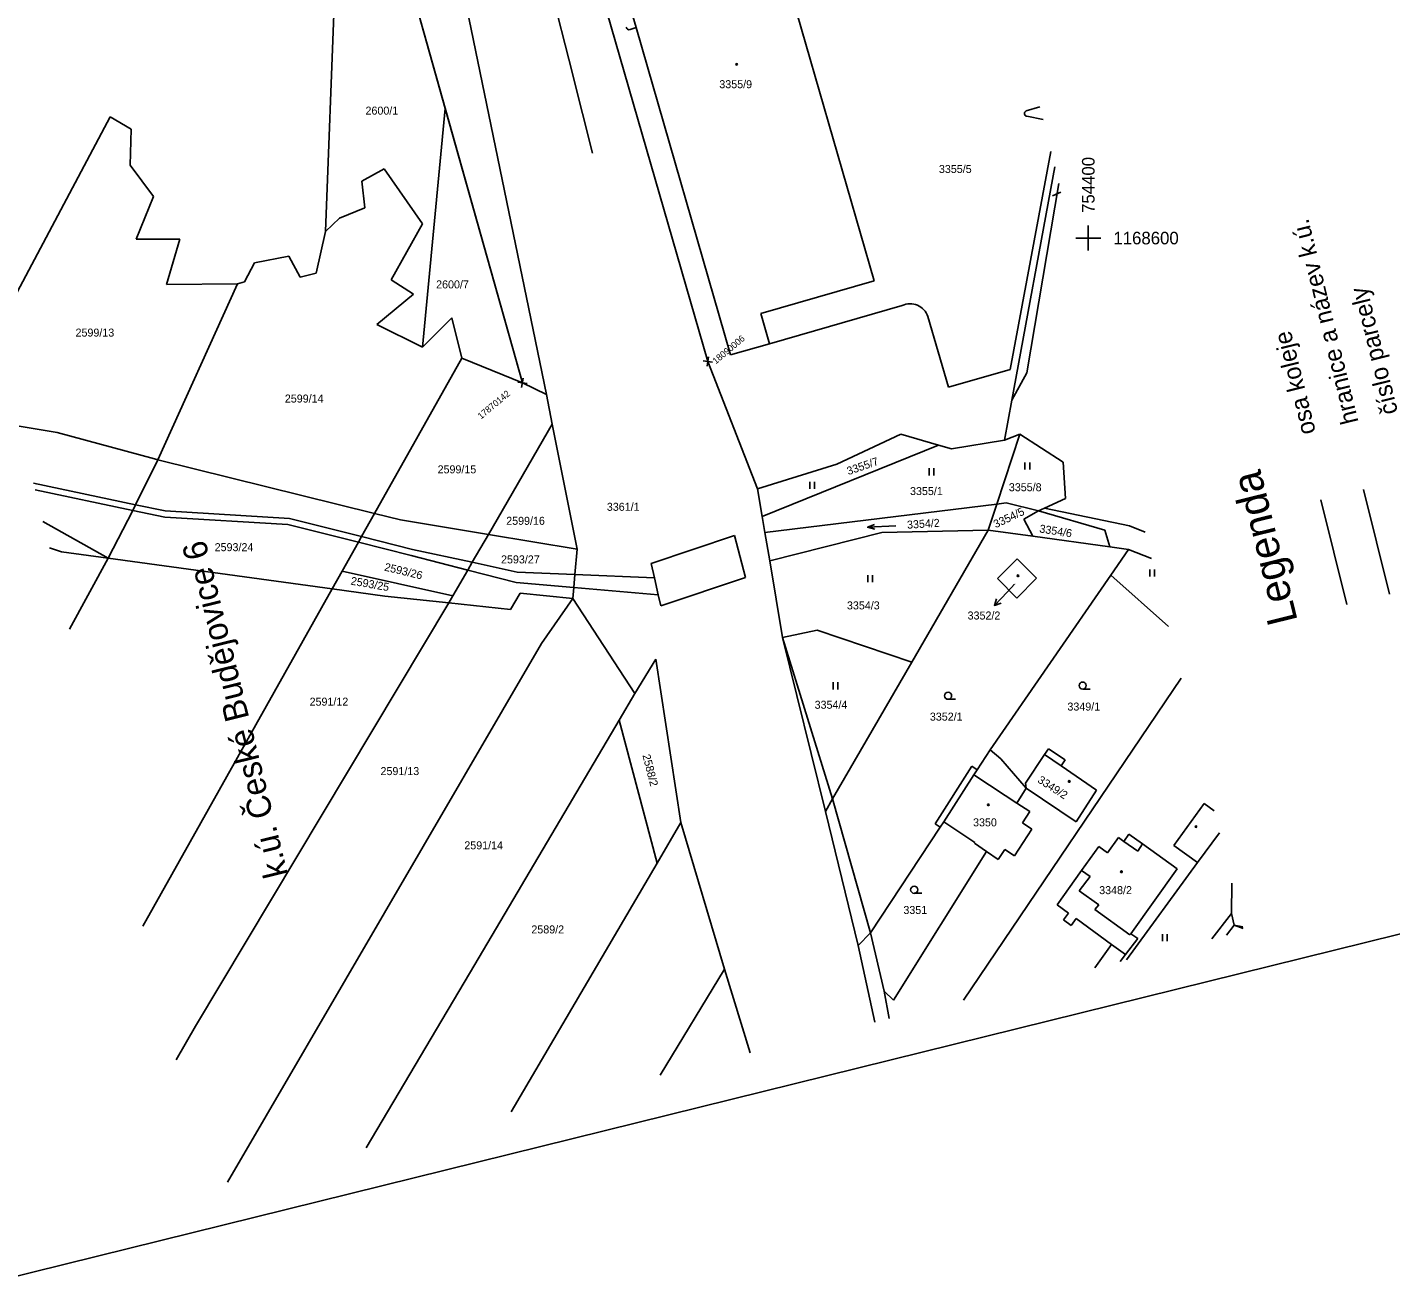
# Model space of a CAD drawing. Extents: x -754679 to -754173, y -1169241 to -1168288.
# Drawn here: x -754569 to -754351.8, y -1168767.3 to -1168566.4 of the extents above; entities that cross this region are included whole.
import ezdxf

# ---------------------------------------------------------------- set-up
doc = ezdxf.new("R2010")
doc.units = 0
for name, color, linetype in [('Default', 7, 'Continuous'), ('Vrstva 1', 7, 'Continuous'), ('Vrstva 16', 7, 'Continuous'), ('Vrstva 18', 7, 'Continuous'), ('Vrstva 19', 7, 'Continuous'), ('Vrstva 24', 7, 'Continuous'), ('Vrstva 25', 7, 'Continuous'), ('Vrstva 27', 7, 'Continuous'), ('Vrstva 4', 7, 'Continuous'), ('Vrstva 52', 7, 'Continuous'), ('Vrstva 53', 7, 'Continuous'), ('Vrstva 6', 7, 'Continuous'), ('Vrstva 60', 7, 'Continuous'), ('Vrstva 61', 7, 'Continuous')]:
    doc.layers.add(name, color=color, linetype=linetype)

msp = doc.modelspace()

# ---------------------------------------------------------------- linework, layer by layer
at = {"layer": 'Default'}
for points in [[(-754400, -1168602), (-754400, -1168600), (-754400, -1168598)], [(-754402, -1168600), (-754400, -1168600), (-754398, -1168600)]]:
    msp.add_lwpolyline(points, dxfattribs=at)
at = {"layer": 'Vrstva 1'}
for p, q in [((-754519.8, -1168462.41), (-754486.32, -1168624.94)), ((-754502.42, -1168579.34), (-754515.13, -1168534.05)), ((-754483.21, -1168541.23), (-754460.6, -1168619.67)), ((-754472.02, -1168566.47), (-754478.33, -1168544.59)), ((-754447.41, -1168560.64), (-754434.1, -1168606.84)), ((-754472.98, -1168566.77), (-754472.02, -1168566.47)), ((-754456.98, -1168618.63), (-754472.02, -1168566.47)), ((-754490.14, -1168623.07), (-754502.42, -1168579.34)), ((-754409.87, -1168579.74), (-754407.71, -1168579.09)), ((-754407.21, -1168581.12), (-754409.78, -1168580.6)), ((-754412.42, -1168620.92), (-754405.96, -1168586.18)), ((-754405.35, -1168588.64), (-754412.19, -1168625.83)), ((-754404.69, -1168591.31), (-754409.8, -1168621.48)), ((-754434.1, -1168606.84), (-754452.14, -1168612.04)), ((-754452.14, -1168612.04), (-754450.76, -1168616.84)), ((-754450.76, -1168616.84), (-754429.64, -1168610.75)), ((-754425.55, -1168612.51), (-754422.27, -1168623.78)), ((-754450.76, -1168616.84), (-754456.98, -1168618.63)), ((-754460.6, -1168619.67), (-754452.67, -1168639.96)), ((-754422.27, -1168623.78), (-754412.42, -1168620.92)), ((-754409.8, -1168621.48), (-754412.19, -1168625.83)), ((-754490.14, -1168623.07), (-754486.32, -1168624.94)), ((-754486.32, -1168624.94), (-754485.38, -1168629.68)), ((-754412.19, -1168625.83), (-754413.36, -1168632.2)), ((-754570.29, -1168629.95), (-754564.24, -1168630.96)), ((-754564.24, -1168630.96), (-754548.76, -1168635.2)), ((-754485.38, -1168629.68), (-754481.43, -1168649.55)), ((-754440.06, -1168636.05), (-754429.88, -1168631.27)), ((-754429.88, -1168631.27), (-754423.86, -1168633.01)), ((-754413.36, -1168632.2), (-754410.89, -1168631.27)), ((-754410.89, -1168631.27), (-754404, -1168635.7)), ((-754423.86, -1168633.01), (-754421.81, -1168633.6)), ((-754421.81, -1168633.6), (-754413.36, -1168632.2)), ((-754548.23, -1168635.33), (-754548.76, -1168635.2)), ((-754513.7, -1168643.9), (-754548.23, -1168635.33)), ((-754404, -1168635.7), (-754403.6, -1168641.5)), ((-754452.67, -1168639.96), (-754440.06, -1168636.05)), ((-754452.67, -1168639.96), (-754451.93, -1168644.34)), ((-754414.55, -1168642.38), (-754451.5, -1168646.92)), ((-754413.07, -1168642.2), (-754414.55, -1168642.38)), ((-754407.94, -1168643.48), (-754413.07, -1168642.2)), ((-754403.6, -1168641.5), (-754406.98, -1168643.04)), ((-754509.58, -1168644.92), (-754513.7, -1168643.9)), ((-754451.93, -1168644.34), (-754451.5, -1168646.92)), ((-754406.98, -1168643.04), (-754407.94, -1168643.48)), ((-754406.98, -1168643.04), (-754393.41, -1168645.86)), ((-754495.56, -1168647.23), (-754509.58, -1168644.92)), ((-754432.9, -1168646.9), (-754415.92, -1168646.53)), ((-754415.92, -1168646.53), (-754428.1, -1168667.57)), ((-754408.83, -1168647.52), (-754415.92, -1168646.53)), ((-754393.41, -1168645.86), (-754390.96, -1168646.85)), ((-754481.43, -1168649.55), (-754495.56, -1168647.23)), ((-754451.5, -1168646.92), (-754450.74, -1168651.41)), ((-754432.9, -1168646.9), (-754450.74, -1168651.41)), ((-754396.58, -1168649.22), (-754408.83, -1168647.52)), ((-754563.56, -1168649.98), (-754565.48, -1168649.38)), ((-754563.56, -1168649.98), (-754556.15, -1168651.01)), ((-754556.15, -1168651.01), (-754520.42, -1168655.89)), ((-754481.43, -1168649.55), (-754481.76, -1168653.61)), ((-754411.33, -1168651.11), (-754414.47, -1168654.27)), ((-754408.23, -1168654.21), (-754411.33, -1168651.11)), ((-754393.6, -1168649.63), (-754396.58, -1168649.22)), ((-754393.6, -1168649.63), (-754396.4, -1168653.69)), ((-754393.6, -1168649.63), (-754389.92, -1168651.06)), ((-754448.68, -1168663.63), (-754450.74, -1168651.41)), ((-754481.76, -1168653.61), (-754481.94, -1168655.69)), ((-754396.4, -1168653.69), (-754415.64, -1168681.53)), ((-754414.47, -1168654.27), (-754411.38, -1168657.36)), ((-754411.38, -1168657.36), (-754408.23, -1168654.21)), ((-754396.4, -1168653.69), (-754387.23, -1168661.91)), ((-754520.42, -1168655.89), (-754512.05, -1168657.04)), ((-754512.05, -1168657.04), (-754501.88, -1168658.12)), ((-754492.02, -1168659.16), (-754490.52, -1168656.57)), ((-754490.52, -1168656.57), (-754482.08, -1168657.45)), ((-754481.94, -1168655.69), (-754482.08, -1168657.45)), ((-754472.22, -1168672.58), (-754482.08, -1168657.45)), ((-754501.88, -1168658.12), (-754492.02, -1168659.16)), ((-754448.68, -1168663.63), (-754441.87, -1168691.36)), ((-754468.86, -1168667.12), (-754472.22, -1168672.58)), ((-754464.89, -1168693.12), (-754468.86, -1168667.12)), ((-754428.1, -1168667.57), (-754440.72, -1168689.36)), ((-754385.2, -1168670.12), (-754419.89, -1168721.45)), ((-754472.22, -1168672.58), (-754474.73, -1168676.83)), ((-754497.71, -1168715.77), (-754474.73, -1168676.83)), ((-754474.73, -1168676.83), (-754468.68, -1168699.59)), ((-754415.64, -1168681.53), (-754417.68, -1168684.71)), ((-754415.64, -1168681.53), (-754413.94, -1168682.99)), ((-754406.97, -1168682.3), (-754406.35, -1168681.37)), ((-754406.35, -1168681.37), (-754403.66, -1168683.16)), ((-754413.94, -1168682.99), (-754409.88, -1168687.67)), ((-754410.01, -1168686.86), (-754406.97, -1168682.3)), ((-754403.66, -1168683.16), (-754404.29, -1168684.1)), ((-754418.53, -1168684.17), (-754424.41, -1168693.34)), ((-754417.68, -1168684.71), (-754418.53, -1168684.17)), ((-754404.29, -1168684.1), (-754398.67, -1168687.96)), ((-754409.88, -1168687.67), (-754411.36, -1168690.04)), ((-754409.88, -1168687.67), (-754410.01, -1168686.86)), ((-754401.94, -1168693.01), (-754409.88, -1168687.67)), ((-754398.67, -1168687.96), (-754401.94, -1168693.01)), ((-754440.72, -1168689.36), (-754441.87, -1168691.36)), ((-754411.36, -1168690.04), (-754409.3, -1168691.38)), ((-754381.55, -1168690.12), (-754386.35, -1168696.77)), ((-754379.97, -1168691.28), (-754381.55, -1168690.12)), ((-754436.63, -1168712.73), (-754441.87, -1168691.36)), ((-754409.3, -1168691.38), (-754410.48, -1168693.2)), ((-754468.68, -1168699.59), (-754464.89, -1168693.12)), ((-754464.89, -1168693.12), (-754457.95, -1168716.5)), ((-754423.57, -1168693.88), (-754434.7, -1168710.71)), ((-754424.41, -1168693.34), (-754423.57, -1168693.88)), ((-754423.03, -1168693.04), (-754423.57, -1168693.88)), ((-754418.08, -1168696.32), (-754423.03, -1168693.04)), ((-754408.98, -1168694.18), (-754411.76, -1168698.45)), ((-754410.48, -1168693.2), (-754408.98, -1168694.18)), ((-754418.1, -1168696.41), (-754418.08, -1168696.32)), ((-754416.19, -1168697.75), (-754418.1, -1168696.41)), ((-754395.18, -1168695.53), (-754396.93, -1168697.95)), ((-754394.33, -1168696.13), (-754395.18, -1168695.53)), ((-754393.52, -1168694.99), (-754394.33, -1168696.13)), ((-754391.34, -1168696.54), (-754393.52, -1168694.99)), ((-754385.86, -1168700.53), (-754391.34, -1168696.54)), ((-754386.35, -1168696.77), (-754382.58, -1168699.52)), ((-754382.58, -1168699.52), (-754379.11, -1168694.75)), ((-754416.19, -1168697.75), (-754431.01, -1168721.45)), ((-754414.34, -1168699.04), (-754416.19, -1168697.75)), ((-754413.3, -1168697.45), (-754414.34, -1168699.04)), ((-754411.76, -1168698.45), (-754413.3, -1168697.45)), ((-754398.33, -1168696.96), (-754401.06, -1168700.75)), ((-754396.93, -1168697.95), (-754398.33, -1168696.96)), ((-754491.91, -1168739.25), (-754468.68, -1168699.59)), ((-754401.06, -1168700.75), (-754404.95, -1168706.25)), ((-754393.89, -1168715.02), (-754382.58, -1168699.52)), ((-754393.21, -1168710.84), (-754385.86, -1168700.53)), ((-754377.12, -1168702.79), (-754377.2, -1168707.6)), ((-754404.95, -1168706.25), (-754403.16, -1168707.56)), ((-754403.16, -1168707.56), (-754403.96, -1168708.65)), ((-754377.2, -1168707.6), (-754380.33, -1168711.66)), ((-754376.74, -1168709.5), (-754377.2, -1168707.6)), ((-754403.96, -1168708.65), (-754402.75, -1168709.54)), ((-754402.75, -1168709.54), (-754401.95, -1168708.44)), ((-754401.95, -1168708.44), (-754396.29, -1168712.57)), ((-754376.74, -1168709.5), (-754375.34, -1168710.03)), ((-754434.7, -1168710.71), (-754436.63, -1168712.73)), ((-754434.7, -1168710.71), (-754432.51, -1168719.99)), ((-754394.09, -1168714.17), (-754392.08, -1168711.61)), ((-754392.08, -1168711.61), (-754393.21, -1168710.84)), ((-754436.63, -1168712.73), (-754433.99, -1168724.93)), ((-754398.96, -1168716.27), (-754396.29, -1168712.57)), ((-754396.29, -1168712.57), (-754394.09, -1168714.17)), ((-754394.09, -1168714.17), (-754394.9, -1168715.27)), ((-754515.02, -1168744.97), (-754497.71, -1168715.77)), ((-754457.95, -1168716.5), (-754468.2, -1168733.39)), ((-754457.95, -1168716.5), (-754453.86, -1168729.85)), ((-754431.01, -1168721.45), (-754432.51, -1168719.99)), ((-754545.31, -1168730.96), (-754542.2, -1168725.58))]:
    msp.add_line(p, q, dxfattribs=at)
msp.add_lwpolyline([(-754478.97, -1168586.46), (-754480.56, -1168580.17), (-754482.76, -1168571.47), (-754485.13, -1168562.12), (-754486.61, -1168556.26), (-754487.79, -1168551.61), (-754490, -1168542.89), (-754492.27, -1168533.93), (-754493.96, -1168527.25), (-754496.18, -1168518.51), (-754498.39, -1168509.75)], dxfattribs=at)
for centre, radius, start, end in [((-754473.14, -1168566.34), 0.458, 188.7847, 290.1201), ((-754409.71, -1168580.16), 0.449, 111.4818, 260.4669), ((-754428.36, -1168613.4), 2.94, 17.5572, 115.8766)]:
    msp.add_arc(centre, radius, start, end, dxfattribs=at)
at = {"layer": 'Vrstva 16'}
for p, q in [((-754405.69, -1168593.28), (-754404.35, -1168592.69)), ((-754411.74, -1168655.16), (-754412.88, -1168656.36)), ((-754414.94, -1168658.54), (-754412.88, -1168656.36))]:
    msp.add_line(p, q, dxfattribs=at)
msp.add_lwpolyline([(-754413.89, -1168658.16), (-754414.94, -1168658.54), (-754414.62, -1168657.47)], dxfattribs=at)
at = {"layer": 'Vrstva 24'}
msp.add_line((-754352.02, -1168656.73), (-754356.14, -1168640.06), dxfattribs=at)
at = {"layer": 'Vrstva 25'}
for p, q in [((-754410.08, -1168636.9), (-754410.08, -1168635.78)), ((-754409.33, -1168636.9), (-754409.33, -1168635.78)), ((-754425.35, -1168637.81), (-754425.35, -1168636.69)), ((-754424.6, -1168637.81), (-754424.6, -1168636.69)), ((-754444.36, -1168639.95), (-754444.36, -1168638.82)), ((-754443.61, -1168639.95), (-754443.61, -1168638.82)), ((-754390.18, -1168653.94), (-754390.18, -1168652.81)), ((-754389.43, -1168653.94), (-754389.43, -1168652.81)), ((-754435.1, -1168654.85), (-754435.1, -1168653.73)), ((-754434.35, -1168654.85), (-754434.35, -1168653.73)), ((-754440.64, -1168671.92), (-754440.64, -1168670.79)), ((-754439.89, -1168671.92), (-754439.89, -1168670.79)), ((-754400.89, -1168671.86), (-754399.69, -1168671.86)), ((-754422.33, -1168673.49), (-754421.13, -1168673.49)), ((-754427.73, -1168704.41), (-754426.53, -1168704.41)), ((-754388.2, -1168712.05), (-754388.2, -1168710.93)), ((-754387.45, -1168712.05), (-754387.45, -1168710.93))]:
    msp.add_line(p, q, dxfattribs=at)
for points in [[(-754435.14, -1168646.09), (-754434.03, -1168645.66)], [(-754430.64, -1168645.85), (-754435.14, -1168646.09), (-754433.99, -1168646.41)]]:
    msp.add_lwpolyline(points, dxfattribs=at)
for centre, radius in [((-754456.02, -1168572.33), 0.131), ((-754411.19, -1168653.81), 0.131), ((-754400.89, -1168671.3), 0.562), ((-754422.33, -1168672.93), 0.562), ((-754403.03, -1168686.58), 0.131), ((-754415.93, -1168690.31), 0.131), ((-754382.84, -1168693.79), 0.131), ((-754394.71, -1168700.98), 0.131), ((-754427.73, -1168703.85), 0.562)]:
    msp.add_circle(centre, radius, dxfattribs=at)
at = {"layer": 'Vrstva 27'}
msp.add_line((-754358.81, -1168658.41), (-754362.94, -1168641.73), dxfattribs=at)
at = {"layer": 'Vrstva 4'}
for p, q in [((-754568.04, -1168639.05), (-754551.77, -1168642.49)), ((-754567.77, -1168640.13), (-754552.22, -1168643.4)), ((-754551.77, -1168642.49), (-754547.06, -1168643.48)), ((-754552.22, -1168643.4), (-754547.12, -1168644.47)), ((-754547.12, -1168644.47), (-754527.5, -1168645.65)), ((-754547.06, -1168643.48), (-754527.26, -1168644.67)), ((-754527.26, -1168644.67), (-754515.75, -1168647.56)), ((-754527.5, -1168645.65), (-754516.26, -1168648.47)), ((-754516.26, -1168648.47), (-754507.88, -1168650.57)), ((-754515.75, -1168647.56), (-754507.64, -1168649.6)), ((-754469.63, -1168651.87), (-754456.36, -1168647.37)), ((-754456.36, -1168647.37), (-754454.61, -1168654.08)), ((-754507.88, -1168650.57), (-754498.85, -1168652.9)), ((-754507.64, -1168649.6), (-754498.13, -1168651.66)), ((-754498.85, -1168652.9), (-754491.11, -1168654.89)), ((-754498.13, -1168651.66), (-754490.96, -1168653.21)), ((-754490.96, -1168653.21), (-754481.76, -1168653.61)), ((-754469.63, -1168651.87), (-754469.11, -1168654.15)), ((-754491.11, -1168654.89), (-754481.94, -1168655.69)), ((-754481.76, -1168653.61), (-754469.11, -1168654.15)), ((-754469.11, -1168654.15), (-754468.49, -1168656.87)), ((-754468.1, -1168658.6), (-754454.61, -1168654.08)), ((-754481.94, -1168655.69), (-754468.49, -1168656.87)), ((-754468.1, -1168658.6), (-754468.49, -1168656.87)), ((-754440.72, -1168689.36), (-754448.68, -1168663.63)), ((-754406.97, -1168682.3), (-754404.29, -1168684.1)), ((-754418.22, -1168685.55), (-754423.03, -1168693.04)), ((-754417.68, -1168684.71), (-754418.22, -1168685.55)), ((-754418.22, -1168685.55), (-754413.25, -1168688.81)), ((-754440.72, -1168689.36), (-754434.7, -1168710.71)), ((-754413.25, -1168688.81), (-754411.36, -1168690.04)), ((-754392.13, -1168697.71), (-754394.33, -1168696.13)), ((-754391.34, -1168696.54), (-754392.13, -1168697.71)), ((-754401.06, -1168700.75), (-754399.72, -1168701.74)), ((-754399.72, -1168701.74), (-754401.46, -1168704.02)), ((-754401.46, -1168704.02), (-754398.34, -1168706.25)), ((-754398.34, -1168706.25), (-754398.97, -1168706.99)), ((-754398.97, -1168706.99), (-754393.36, -1168711.05)), ((-754377.98, -1168711.08), (-754376.74, -1168709.5)), ((-754393.36, -1168711.05), (-754393.21, -1168710.84)), ((-754431.69, -1168724.36), (-754432.51, -1168719.99))]:
    msp.add_line(p, q, dxfattribs=at)
at = {"layer": 'Vrstva 53'}
for p, q in [((-754490.14, -1168623.07), (-754523.85, -1168502.96)), ((-754483.21, -1168541.23), (-754460.6, -1168619.67))]:
    msp.add_line(p, q, dxfattribs=at)
at = {"layer": 'Vrstva 6'}
for p, q in [((-754521.52, -1168598.96), (-754519.11, -1168536.88)), ((-754506.06, -1168617.39), (-754502.42, -1168579.34)), ((-754574, -1168614.95), (-754555.83, -1168580.68)), ((-754555.83, -1168580.68), (-754552.45, -1168582.65)), ((-754552.45, -1168582.65), (-754552.61, -1168588.39)), ((-754552.61, -1168588.39), (-754548.9, -1168593.37)), ((-754515.73, -1168590.96), (-754512.18, -1168588.99)), ((-754512.18, -1168588.99), (-754506.06, -1168597.75)), ((-754515.24, -1168595.19), (-754515.73, -1168590.96)), ((-754548.9, -1168593.37), (-754551.64, -1168600.17)), ((-754521.52, -1168598.96), (-754519.27, -1168596.85)), ((-754519.27, -1168596.85), (-754515.24, -1168595.19)), ((-754522.97, -1168605.61), (-754521.52, -1168598.96)), ((-754506.06, -1168597.75), (-754511.06, -1168606.67)), ((-754551.64, -1168600.17), (-754544.72, -1168600.17)), ((-754544.72, -1168600.17), (-754546.81, -1168607.42)), ((-754532.8, -1168603.95), (-754527.32, -1168602.89)), ((-754527.32, -1168602.89), (-754525.55, -1168606.21)), ((-754534.41, -1168606.97), (-754532.8, -1168603.95)), ((-754548.23, -1168635.33), (-754535.54, -1168607.27)), ((-754546.81, -1168607.42), (-754535.54, -1168607.27)), ((-754535.54, -1168607.27), (-754534.41, -1168606.97)), ((-754525.55, -1168606.21), (-754522.97, -1168605.61)), ((-754511.06, -1168606.67), (-754507.51, -1168608.93)), ((-754507.51, -1168608.93), (-754513.31, -1168613.76)), ((-754513.31, -1168613.76), (-754506.06, -1168617.39)), ((-754506.06, -1168617.39), (-754501.39, -1168612.71)), ((-754501.39, -1168612.71), (-754499.81, -1168619.14)), ((-754499.81, -1168619.14), (-754513.7, -1168643.9)), ((-754499.81, -1168619.14), (-754490.14, -1168623.07)), ((-754485.38, -1168629.68), (-754495.56, -1168647.23)), ((-754410.89, -1168631.27), (-754414.55, -1168642.38)), ((-754451.93, -1168644.34), (-754423.86, -1168633.01)), ((-754551.77, -1168642.49), (-754548.23, -1168635.33)), ((-754552.22, -1168643.4), (-754551.77, -1168642.49)), ((-754414.55, -1168642.38), (-754415.92, -1168646.53)), ((-754552.22, -1168643.4), (-754556.15, -1168651.01)), ((-754513.7, -1168643.9), (-754515.75, -1168647.56)), ((-754407.94, -1168643.48), (-754410.28, -1168644.8)), ((-754397.37, -1168646.53), (-754407.94, -1168643.48)), ((-754566.53, -1168645.15), (-754556.15, -1168651.01)), ((-754410.28, -1168644.8), (-754408.83, -1168647.52)), ((-754396.58, -1168649.22), (-754397.37, -1168646.53)), ((-754516.26, -1168648.47), (-754518.85, -1168653.1)), ((-754515.75, -1168647.56), (-754516.26, -1168648.47)), ((-754495.56, -1168647.23), (-754498.13, -1168651.66)), ((-754562.29, -1168662.3), (-754556.15, -1168651.01)), ((-754518.85, -1168653.1), (-754520.42, -1168655.89)), ((-754518.85, -1168653.1), (-754501.23, -1168657.01)), ((-754498.85, -1168652.9), (-754501.23, -1168657.01)), ((-754498.13, -1168651.66), (-754498.85, -1168652.9)), ((-754520.42, -1168655.89), (-754550.58, -1168709.63)), ((-754501.23, -1168657.01), (-754501.88, -1168658.12)), ((-754482.08, -1168657.45), (-754487.11, -1168664.61)), ((-754542.2, -1168725.58), (-754501.88, -1168658.12)), ((-754448.68, -1168663.63), (-754443.21, -1168662.48)), ((-754443.21, -1168662.48), (-754428.1, -1168667.57)), ((-754487.11, -1168664.61), (-754537.11, -1168750.43)), ((-754375.4, -1168709.77), (-754376.74, -1168709.5))]:
    msp.add_line(p, q, dxfattribs=at)
at = {"layer": 'Vrstva 60'}
for p, q in [((-754461.34, -1168619.54), (-754459.86, -1168619.8)), ((-754460.47, -1168618.93), (-754460.73, -1168620.41)), ((-754490.88, -1168622.94), (-754489.4, -1168623.2)), ((-754490.01, -1168622.33), (-754490.27, -1168623.81))]:
    msp.add_line(p, q, dxfattribs=at)
at = {"layer": 'Vrstva 61'}
msp.add_lwpolyline([(-754578.24, -1168767.26), (-754289.93, -1168695.96), (-754390.75, -1168288.24), (-754679.07, -1168359.54)], dxfattribs=at)

# ---------------------------------------------------------------- texts
at = {"layer": 'Default'}
msp.add_text('754400', height=2, rotation=90, dxfattribs=at).set_placement((-754399, -1168596))
msp.add_text('1168600', height=2, dxfattribs=at).set_placement((-754396, -1168601))
at = {"layer": 'Vrstva 16'}
msp.add_text('3352/2', height=1.275, rotation=360, dxfattribs=at).set_placement((-754419.22, -1168660.78))
at = {"layer": 'Vrstva 18'}
for s, rotation, p in [('2600/1', 360, (-754515.13, -1168580.33)), ('3355/5', 360, (-754423.79, -1168589.63)), ('2600/7', 360, (-754503.88, -1168608.02)), ('2599/13', 360, (-754561.32, -1168615.7)), ('2599/14', 360, (-754527.98, -1168626.21)), ('3355/7', 18.9076, (-754438.21, -1168637.78)), ('2599/15', 360, (-754503.65, -1168637.49)), ('3355/1', 360, (-754428.39, -1168640.95)), ('3355/8', 360, (-754412.65, -1168640.34)), ('3361/1', 360, (-754476.69, -1168643.46)), ('2599/16', 360, (-754492.72, -1168645.69)), ('3354/5', 25.4966, (-754414.73, -1168646.25)), ('3354/2', 3.6096, (-754428.83, -1168646.32)), ('3354/6', 350.9939, (-754407.85, -1168646.89)), ('2593/24', 360, (-754539.16, -1168649.89)), ('2593/27', 360, (-754493.54, -1168651.84)), ('2593/26', 346.5249, (-754512.22, -1168652.97)), ('2593/25', 350.0772, (-754517.56, -1168655.21)), ('3354/3', 360, (-754438.44, -1168659.17)), ('2591/12', 360, (-754524.04, -1168674.51)), ('3354/4', 360, (-754443.59, -1168675)), ('3349/1', 360, (-754403.32, -1168675.29)), ('3352/1', 360, (-754425.23, -1168676.89)), ('2588/2', 284.4162, (-754471.03, -1168682.42)), ('2591/13', 360, (-754512.74, -1168685.57)), ('2591/14', 360, (-754499.39, -1168697.4)), ('3351', 360, (-754429.45, -1168707.7)), ('2589/2', 360, (-754488.71, -1168710.8))]:
    msp.add_text(s, height=1.275, rotation=rotation, dxfattribs=at).set_placement(p)
msp.add_text('3355/10', height=0.1, dxfattribs=at).set_placement((-754405.68, -1168593.28))
at = {"layer": 'Vrstva 19'}
for s, rotation, p in [('3355/9', 360, (-754458.77, -1168576.12)), ('3349/2', 327.1016, (-754408.18, -1168686.65)), ('3350', 360, (-754418.35, -1168693.74)), ('3348/2', 360, (-754398.26, -1168704.54))]:
    msp.add_text(s, height=1.275, rotation=rotation, dxfattribs=at).set_placement(p)
msp.add_text('3352/2', height=0.1, dxfattribs=at).set_placement((-754412, -1168655.16))
at = {"layer": 'Vrstva 24'}
msp.add_text('k.ú. České Budějovice 6', height=3.84, rotation=103.8896, dxfattribs=at).set_placement((-754527.46, -1168701.42))
at = {"layer": 'Vrstva 27'}
for s, height, rotation, p in [('hranice a název k.ú.', 2.8, 103.8896, (-754356.93, -1168629.28)), ('číslo parcely', 2.8, 103.8896, (-754350.64, -1168627.78)), ('osa koleje', 2.8, 103.8896, (-754363.73, -1168630.96)), ('Legenda', 4.8, 103.9106, (-754366.61, -1168660.98))]:
    msp.add_text(s, height=height, rotation=rotation, dxfattribs=at).set_placement(p)
at = {"layer": 'Vrstva 52'}
for s, p in [(' 18090006', (-754459.62, -1168620.39)), (' 17870142', (-754497.02, -1168629.18))]:
    msp.add_text(s, height=1.037, rotation=40, dxfattribs=at).set_placement(p)

doc.saveas('drawing.dxf')
